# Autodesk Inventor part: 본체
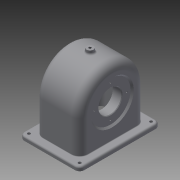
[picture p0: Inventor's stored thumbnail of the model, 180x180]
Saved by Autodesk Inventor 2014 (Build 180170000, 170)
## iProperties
Created: 2016-01
Part Number: 본체
Material: Generic
Document SubType Name: Modeling
Designer: 04
Density: 1 g/cm^3
Appearance: Default
Author: 04
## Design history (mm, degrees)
sketch "스케치1"
  geometry: L1 (-57, 0)-(-57, 64); L2 (57, 64)-(57, 0); L3 (57, 0)-(-57, 0); A1 r 57 centre (0, 64) between (57, 64) and (-57, 64); 2 further points
  constraints: 6 end point, 2 point on circle, 2 tangent, 1 centre point, 1 coincident, 1 midpoint, 1 parallel, 1 perpendicular, 1 vertical
  dimensions: "d0" = 64 distance of L1.start L1.end; "d2" = 114 distance of L2.end L1.start
extrude "돌출1" new body sketch "스케치1" stored distance "d3" = 77; taper "d4" = 0 deg
sketch "스케치3"
  geometry: L1 (-57, 0)-(-57, 64) reference; L2 (57, 0)-(-57, 0) reference; L3 (57, 64)-(57, 0) reference; L4 (51, 64)-(51, 0); L5 (-51, 0)-(-51, 64); A1 r 57 centre (0, 64) between (57, 64) and (-57, 64) reference; A2 r 51 centre (0, 64) between (51, 64) and (-51, 64); 1 further point
  constraints: 4 end point, 2 point on circle, 2 point on line, 1 centre point, 1 parallel, 1 perpendicular, 1 tangent
  dimensions: "d5" = 6 distance between parallel lines of L1 L5; "d6" = 6 distance between parallel lines of L3 L4
extrude "돌출2" cut sketch "스케치3" stored distance "d7" = 67; taper "d8" = 0 deg
sketch "스케치4"
  geometry: L1 (72, -6)-(72, -108) reference; L2 (72, -108)-(5, -108) reference; L3 (5, -108)-(5, -6) reference; L4 (5, -6)-(72, -6) reference; L5 (90.5, -127)-(-13.5, -127); L6 (-13.5, -127)-(-13.5, 13); L7 (-13.5, 13)-(90.5, 13); L8 (90.5, 13)-(90.5, -127); L9 (90.5, -127)-(-13.5, 13); L10 (-13.5, -127)-(90.5, 13); 1 further point
  constraints: 12 end point, 2 midpoint, 2 parallel, 1 horizontal, 1 perpendicular
  dimensions: "d9" = 104 distance of L6.end L7.end; "d10" = 140 distance of L5.end L6.end
extrude "돌출3" join sketch "스케치4" distance "d11" = 7; taper "d12" = 0 deg
sketch "스케치6"
  geometry: 1 further point
sketch "스케치7"
  geometry: C1 r 31 at (64, 0); A1 r 57 centre (64, 0) between (64, -57) and (64, 57) reference; 1 further point
  constraints: 1 centre point, 1 coincident
  dimensions: "d13" = 62 diameter of C1
extrude "돌출4" join sketch "스케치7" distance "d14" = 10; taper "d15" = 0 deg
sketch "스케치8"
  geometry: L1 (-33.5, 115)-(-33.5, 64) reference; L2 (-33.5, 64)-(-33.5, 0) reference; L3 (48.5, 33)-(48.5, 95) reference; L4 (48.5, 64)-(-33.5, 64); L5 (-38.5, 121)-(-38.5, 64) reference; L6 (-38.5, 64)-(-38.5, 7) reference; L7 (-38.5, 107.943)-(-19.5, 92); L8 (-19.5, 92)-(-19.5, 64); L9 (-19.5, 64)-(-38.5, 64); 3 further points
  constraints: 8 end point, 2 perpendicular, 2 point on line, 1 collinear, 1 midpoint
  dimensions: "d18" = 50 deg angle of L8 L7; "d19" = 19 distance between parallel lines of L5 L8; "d20" = 28 distance of L7.end L8.end
revolve "회전1" sketch "스케치8" stored, may be unused: angle "d21" = 90 deg
sketch "스케치9"
  geometry: L1 (-38.5, 121)-(-38.5, 64) reference; L2 (-38.5, 64)-(-38.5, 7) reference; L3 (48.5, 33)-(48.5, 95) reference; L4 (48.5, 64)-(-38.5, 64); L5 (-33.5, 103.747)-(-19.5, 92) reference; L6 (-38.5, 101.416)-(-35.5, 98.899); L7 (-38.5, 101.416)-(-38.5, 64); L8 (-35.5, 64)-(-35.5, 98.899); L9 (-38.5, 64)-(-35.5, 64); 2 further points
  constraints: 10 end point, 2 collinear, 2 parallel, 2 point on line, 1 midpoint, 1 perpendicular
  dimensions: "d22" = 5 distance between parallel lines of L5 L6; "d23" = 3 distance between parallel lines of L7 L8
revolve "회전2" sketch "스케치9" stored, may be unused: angle "d24" = 90 deg
sketch "스케치10"
  geometry: C1 r 31 at (0, 0) reference; C2 r 20 at (0, 0); 1 further point
  constraints: 1 centre point, 1 coincident
  dimensions: "d25" = 40 diameter of C2
extrude "돌출5" cut sketch "스케치10" stored distance "d26" = 10; taper "d27" = 0 deg
sketch "스케치11"
  geometry: C1 r 20 at (0, 0) reference; 2 further points
  constraints: 1 horizontal alignment
  dimensions: "d28" = 28 distance of C1.centre point (-28, 0)
sketch "스케치12"
  geometry: C1 r 20 at (0, 0) reference; 2 further points
  constraints: 1 horizontal alignment
  dimensions: "d29" = 24 distance of C1.centre point (24, 0)
hole "구멍1" sketch "스케치11" diameter "d30" = 2.459; stored, may be unused: countersink angle "d34" = 90 deg, drill point angle "d36" = 118 deg; dims "d31" = 7, "d32" = 4, "d33" = 2, "d35" = 9
hole "구멍2" sketch "스케치12" diameter "d37" = 2.459; stored, may be unused: countersink angle "d41" = 90 deg, drill point angle "d43" = 118 deg; dims "d38" = 6, "d39" = 4, "d40" = 2, "d42" = 8
node "작업 평면2"
sketch "스케치13"
  geometry: C1 r 6 at (-52, 70); 1 further point
  constraints: 1 centre point, 1 coincident
  dimensions: "d53" = 12 diameter of C1
extrude "돌출6" join sketch "스케치13" stored distance "d54" = 10; taper "d55" = 0 deg
sketch "스케치14"
  geometry: C1 r 6 at (0, 0) reference
hole "구멍3" sketch "스케치14" at (0, 0) diameter "d56" = 4.134; stored, may be unused: countersink angle "d60" = 90 deg, drill point angle "d62" = 118 deg; dims "d57" = 6, "d58" = 4, "d59" = 2, "d61" = 8
fillet "모깎기1" dims "d63" = 8, "d64" = 3, "d65" = 14
fillet "모깎기2" dims "d66" = 3, "d75" = 1
sketch "스케치15"
  geometry: A1 r 8 centre (-82.5, 5) between (-82.5, 13) and (-90.5, 5) reference; A2 r 8 centre (-82.5, -119) between (-90.5, -119) and (-82.5, -127) reference; A3 r 8 centre (5.5, -119) between (5.5, -127) and (13.5, -119) reference; A4 r 8 centre (5.5, 5) between (13.5, 5) and (5.5, 13) reference; 1 further point
hole "구멍4" sketch "스케치15" at (-82.5, -119), (5.5, -119), (5.5, 5), (-82.5, 5) diameter "d68" = 5; stored, may be unused: countersink angle "d72" = 90 deg, drill point angle "d74" = 118 deg; dims "d69" = 6, "d70" = 4, "d71" = 2, "d73" = 8
chamfer "모따기1" distance "d76" = 1; stored, may be unused: second distance "d77" = 2, angle "d78" = 45 deg
fillet "모깎기3" dims "d79" = 9
feature "엠보싱1" dims "d82" = 0.5, "d83" = 0
node "솔리드1"
pattern_circular "원형 패턴1" dims angle "d45" = 360 deg
pattern_circular "원형 패턴2" dims angle "d48" = 360 deg
sketch "스케치16"
  geometry: L1 (68.5, 64)-(-19.5, 64) reference; L2 (63, 0)-(63, 56) reference; L3 (68.5, 64)-(76.5, 64) reference; L4 (38.421, 32.03)-(10.579, 32.03); L5 (10.579, 32.03)-(10.579, 35.97); L6 (10.579, 35.97)-(38.421, 35.97); L7 (38.421, 35.97)-(38.421, 32.03); 1 further point
  constraints: 2 other
other parameters: "d51" = -127
